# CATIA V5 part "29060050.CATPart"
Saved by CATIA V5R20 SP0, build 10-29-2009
Part number: 29060050
Definition: NONE
Nomenclature: 29060050
Source: Unknown
Description: 29060050
Bounding box of the stored display mesh (mm): x -25 to 44.548, y -44 to 78.548, z -34 to 34
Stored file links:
  C:\Users\Utente\Desktop\IO LAVORO\3D X SITO CF\X SITO\PLASTICA\RF1\29060050.CATPart
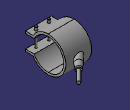
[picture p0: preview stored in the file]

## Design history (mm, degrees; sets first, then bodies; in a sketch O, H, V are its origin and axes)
Body1 "29060050" (main body)
  Solid1: solid without history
